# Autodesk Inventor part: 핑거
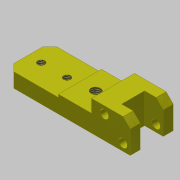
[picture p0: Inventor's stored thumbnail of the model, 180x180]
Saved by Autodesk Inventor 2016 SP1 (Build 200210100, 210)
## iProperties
Created: 2019-02
Part Number: 핑거
Material: 알루미늄 6061
Document SubType Name: Modeling
Designer: mduedu
Density: 1 g/cm^3
Appearance: 노란색
Author: mduedu
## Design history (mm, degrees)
sketch "스케치1"
  geometry: L1 (0, 0)-(-86, 0); L2 (-86, 0)-(-86, 21); L3 (-86, 21)-(0, 21); L4 (0, 21)-(0, 0)
  constraints: 8 end point, 2 parallel, 1 horizontal, 1 perpendicular
  dimensions: "d0" = 86 distance of L2.end L3.end; "d1" = 21 distance of L1.end L2.end
extrude "돌출1" new body sketch "스케치1" stored distance "d2" = 30; taper "d3" = 0 deg
sketch "스케치2"
  geometry: L1 (-86, 0)-(0, 0) reference; L2 (0, 0)-(0, 21) reference; L3 (0, 21)-(-86, 21) reference; L4 (-86, 21)-(-86, 0) reference; L5 (-86, 10)-(-50, 10); L6 (-50, 10)-(-50, 21); L7 (-50, 21)-(-86, 21); L8 (-86, 21)-(-86, 10); L9 (-50, 12)-(-27, 12); L10 (-27, 12)-(-27, 21); L11 (-27, 21)-(-50, 21); L12 (-50, 21)-(-50, 12); 1 further point
  constraints: 16 end point, 4 parallel, 4 point on line, 2 horizontal, 2 perpendicular
  dimensions: "d4" = 27 distance between parallel lines of L10 L2; "d5" = 12 distance between parallel lines of L1 L9; "d6" = 36 distance between parallel lines of L6 L4; "d7" = 10 distance between parallel lines of L1 L5
extrude "돌출2" cut sketch "스케치2" stored distance "d8" = 30; taper "d9" = 0 deg
chamfer "모따기1" distance "d10" = 5; stored, may be unused: second distance "d11" = 2, angle "d12" = 45 deg
sketch "스케치3"
  geometry: L1 (27, 0)-(27, 30) reference; L2 (27, 23)-(14, 23); L3 (14, 23)-(14, 7); L4 (14, 7)-(27, 7); L5 (27, 7)-(27, 23); 2 further points
  constraints: 8 end point, 2 midpoint, 2 parallel, 1 horizontal, 1 perpendicular, 1 point on line
  dimensions: "d13" = 16 distance between parallel lines of L4 L2; "d15" = 13 distance of L2.start L2.end
extrude "돌출3" cut sketch "스케치3" stored distance "d16" = 30; taper "d17" = 0 deg
sketch "스케치4"
  geometry: 3 further points
  dimensions: "d18" = 5 horizontal distance of point (-5, 5) point (0, 0); "d19" = 5 horizontal distance of point (-5, 5) point (0, 0); "d20" = 11 vertical distance of point (-18, 16) point (-5, 5); "d21" = 13 horizontal distance of point (-18, 16) point (-5, 5)
hole "구멍1" sketch "스케치4" at (-5, 5), (-18, 16) diameter "d22" = 6; stored, may be unused: countersink angle "d26" = 90 deg, drill point angle "d28" = 118 deg; dims "d23" = 6, "d24" = 4, "d25" = 2, "d27" = 8
sketch "스케치5"
  geometry: L1 (0, 0)-(0, 30) reference; 3 further points
  constraints: 2 horizontal alignment
  dimensions: "d29" = 9 distance from line of point (9, 15) L1; "d30" = 18 distance of point (27, 15) point (9, 15)
hole "구멍2" sketch "스케치5" diameter "d31" = 4.917; stored, may be unused: countersink angle "d35" = 90 deg, drill point angle "d37" = 118 deg; dims "d32" = 6, "d33" = 4, "d34" = 2, "d36" = 8
sketch "스케치6"
  geometry: 3 further points
  constraints: 1 horizontal alignment
  dimensions: "d38" = 20 distance of point (11, 15) point (-9, 15)
hole "구멍3" sketch "스케치6" at (11, 15) diameter "d39" = 6.647; stored, may be unused: countersink angle "d43" = 90 deg, drill point angle "d45" = 118 deg; dims "d40" = 6, "d41" = 4, "d42" = 2, "d44" = 8
chamfer "모따기2" distance "d46" = 5; stored, may be unused: second distance "d47" = 2, angle "d48" = 45 deg
node "솔리드1"
node "투영된 루프1"
